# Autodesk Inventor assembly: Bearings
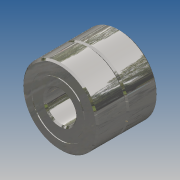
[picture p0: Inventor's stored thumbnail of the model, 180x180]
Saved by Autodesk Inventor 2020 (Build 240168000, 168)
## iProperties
Created: 2019-10
Part Number: Bearings
Document SubType Name: Assembly
Designer: yello
Author: yello
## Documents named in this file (2)
- C:\Users\yello\Documents\Mechanical Hand\Prototype 2 (Realistic Hand)\Bearings.iam
- C:\Users\yello\Downloads\7804K100_STAINLESS STEEL BALL BEARING.ipt
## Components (2 placed, 1 different names)
1. 7804K100_STAINLESS STEEL BALL BEARING:1 — Mate:1, Mate:2
2. 7804K100_STAINLESS STEEL BALL BEARING:2 — Mate:1, Mate:2
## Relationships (2: Mate 2)
- Mate:1: 7804K100_STAINLESS STEEL BALL BEARING:1 ↔ 7804K100_STAINLESS STEEL BALL BEARING:2
- Mate:2: 7804K100_STAINLESS STEEL BALL BEARING:1 ↔ 7804K100_STAINLESS STEEL BALL BEARING:2
